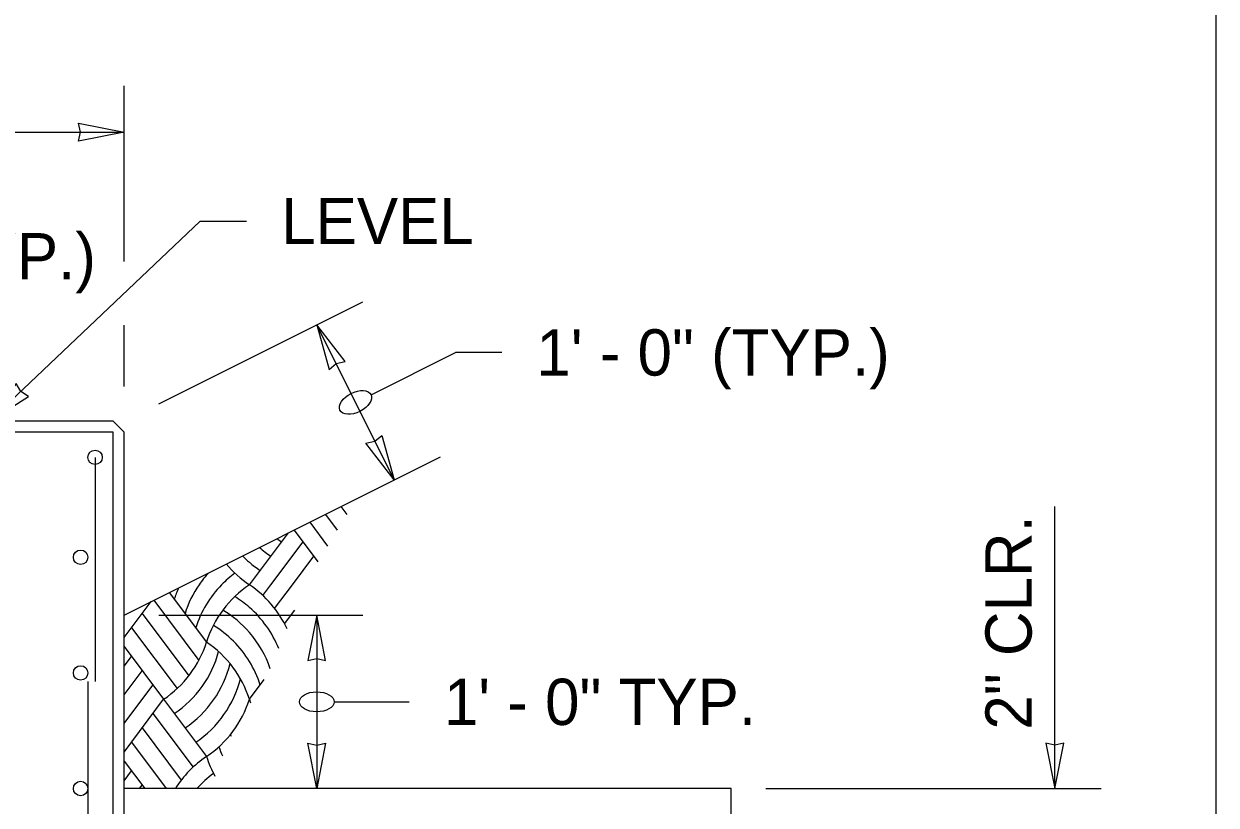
# Model space of a CAD drawing. Extents: x 99862 to 103151, y 100000 to 102076.
# Drawn here: x 102737.5 to 103150, y 101205 to 101475.3 of the extents above; entities that cross this region are included whole.
import ezdxf

# ---------------------------------------------------------------- set-up
doc = ezdxf.new("R2010")
doc.units = 0
for name, color, linetype in [('Level 10', 7, 'Continuous'), ('Level 15', 7, 'Continuous'), ('Level 2', 7, 'Continuous'), ('Level 20', 7, 'Continuous'), ('Level 5', 7, 'Continuous'), ('Level 60', 7, 'Continuous')]:
    doc.layers.add(name, color=color, linetype=linetype)

msp = doc.modelspace()

# ---------------------------------------------------------------- linework, layer by layer
at = {"layer": 'Level 10'}
for p, q in [((102762.17, 101325.3), (102762.17, 101247.8)), ((102762.17, 101325.3), (102762.17, 101247.8)), ((102759.67, 101247.8), (102759.67, 100936.99))]:
    msp.add_line(p, q, dxfattribs=at)
for centre in [(102762.17, 101325.3), (102762.17, 101325.3), (102757.17, 101290.72), (102757.17, 101290.72), (102757.17, 101250.72), (102757.17, 101250.72), (102757.17, 101210.71), (102757.17, 101210.71)]:
    msp.add_circle(centre, 2.5, dxfattribs=at)
at = {"layer": 'Level 15'}
for p, q in [((102772.17, 101393.03), (102772.17, 101453.8)), ((102772.17, 101393.03), (102772.17, 101453.8)), ((102592.17, 101437.8), (102772.17, 101437.8)), ((102592.17, 101437.8), (102772.17, 101437.8)), ((102725.6, 101337.8), (102798.56, 101407.05)), ((102725.6, 101337.8), (102798.56, 101407.05)), ((102798.56, 101407.05), (102814.56, 101407.05)), ((102798.56, 101407.05), (102814.56, 101407.05)), ((102784.17, 101343.8), (102854.84, 101379.13)), ((102784.17, 101343.8), (102854.84, 101379.13)), ((102772.17, 101349.8), (102772.17, 101370.97)), ((102772.17, 101349.8), (102772.17, 101370.97)), ((102865.67, 101317.46), (102838.84, 101371.13)), ((102865.67, 101317.46), (102838.84, 101371.13)), ((102857.62, 101346.98), (102886.84, 101361.59)), ((102857.62, 101346.98), (102886.84, 101361.59)), ((102902.84, 101361.59), (102886.84, 101361.59)), ((102902.84, 101361.59), (102886.84, 101361.59)), ((103094.17, 101210.71), (103094.17, 101308.24)), ((103094.17, 101210.71), (103094.17, 101308.24)), ((102784.17, 101270.71), (102854.84, 101270.71)), ((102784.17, 101270.71), (102854.84, 101270.71)), ((102838.84, 101270.71), (102838.84, 101210.71)), ((102838.84, 101270.71), (102838.84, 101210.71)), ((102844.84, 101240.71), (102870.84, 101240.71)), ((102844.84, 101240.71), (102870.84, 101240.71)), ((102994.17, 101210.71), (103110.17, 101210.71)), ((102994.17, 101210.71), (103110.17, 101210.71))]:
    msp.add_line(p, q, dxfattribs=at)
for points in [[(102772.17, 101437.8), (102756.45, 101434.71), (102757.17, 101437.8), (102756.45, 101440.88)], [(102772.17, 101437.8), (102756.45, 101434.71), (102757.17, 101437.8), (102756.45, 101440.88)], [(102838.84, 101371.13), (102843.11, 101355.69), (102845.55, 101357.72), (102848.63, 101358.44)], [(102838.84, 101371.13), (102843.11, 101355.69), (102845.55, 101357.72), (102848.63, 101358.44)], [(102725.6, 101337.8), (102739.13, 101346.38), (102736.48, 101348.12), (102734.89, 101350.86)], [(102865.67, 101317.46), (102855.88, 101330.15), (102858.96, 101330.88), (102861.4, 101332.91)], [(102865.67, 101317.46), (102855.88, 101330.15), (102858.96, 101330.88), (102861.4, 101332.91)], [(102838.84, 101270.71), (102835.75, 101254.99), (102838.84, 101255.72), (102841.92, 101254.99)], [(102838.84, 101270.71), (102835.75, 101254.99), (102838.84, 101255.72), (102841.92, 101254.99)], [(102838.84, 101210.71), (102835.75, 101226.44), (102838.84, 101225.71), (102841.92, 101226.44)], [(102838.84, 101210.71), (102835.75, 101226.44), (102838.84, 101225.71), (102841.92, 101226.44)], [(103094.17, 101210.71), (103097.26, 101226.44), (103094.17, 101225.71), (103091.09, 101226.44)], [(103094.17, 101210.71), (103097.26, 101226.44), (103094.17, 101225.71), (103091.09, 101226.44)]]:
    msp.add_lwpolyline(points, close=True, dxfattribs=at)
for centre, major_axis in [((102852.26, 101344.3), (5.37, 2.68)), ((102852.26, 101344.3), (5.37, 2.68)), ((102838.84, 101240.71), (6, 0)), ((102838.84, 101240.71), (6, 0))]:
    msp.add_ellipse(centre, major_axis=major_axis, ratio=0.57735, dxfattribs=at)
at = {"layer": 'Level 2'}
for p, q in [((102768.42, 101337.8), (102595.92, 101337.8)), ((102768.42, 101337.8), (102595.92, 101337.8)), ((102768.42, 101337.8), (102772.17, 101334.05)), ((102768.42, 101337.8), (102772.17, 101334.05)), ((102768.42, 101334.05), (102595.92, 101334.05)), ((102768.42, 101334.05), (102595.92, 101334.05)), ((102768.42, 101150.71), (102768.42, 101334.05)), ((102768.42, 101150.71), (102768.42, 101334.05)), ((102772.17, 101150.71), (102772.17, 101334.05)), ((102772.17, 101150.71), (102772.17, 101334.05)), ((102982.17, 101210.71), (102772.17, 101210.71)), ((102982.17, 101210.71), (102772.17, 101210.71)), ((102982.17, 100936.99), (102982.17, 101210.71)), ((102982.17, 100936.99), (102982.17, 101210.71))]:
    msp.add_line(p, q, dxfattribs=at)
at = {"layer": 'Level 5'}
for p, q in [((102772.17, 101270.71), (102881.67, 101325.46)), ((102772.17, 101270.71), (102881.67, 101325.46)), ((102841.83, 101305.55), (102845.93, 101300.09)), ((102841.83, 101305.55), (102845.93, 101300.09)), ((102847.23, 101308.25), (102849.26, 101305.55)), ((102847.23, 101308.25), (102849.26, 101305.55)), ((102836.44, 101302.85), (102842.6, 101294.62)), ((102836.44, 101302.85), (102842.6, 101294.62)), ((102815.56, 101281.18), (102829.03, 101299.15)), ((102815.56, 101281.18), (102829.03, 101299.15)), ((102831.04, 101300.15), (102839.28, 101289.16)), ((102831.04, 101300.15), (102839.28, 101289.16)), ((102822.99, 101281.18), (102834.12, 101296.03)), ((102822.99, 101281.18), (102834.12, 101296.03)), ((102830.41, 101281.18), (102837.83, 101291.08)), ((102830.41, 101281.18), (102837.83, 101291.08)), ((102820.21, 101277.49), (102822.99, 101281.18)), ((102820.21, 101277.49), (102822.99, 101281.18)), ((102824.29, 101273.02), (102830.41, 101281.18)), ((102824.29, 101273.02), (102830.41, 101281.18)), ((102782.44, 101275.85), (102798.04, 101255.05)), ((102782.44, 101275.85), (102798.04, 101255.05)), ((102787.84, 101278.55), (102800.71, 101261.38)), ((102787.84, 101278.55), (102800.71, 101261.38)), ((102772.17, 101262.93), (102781.52, 101275.39)), ((102772.17, 101262.93), (102781.52, 101275.39)), ((102827.74, 101267.72), (102831.3, 101272.46)), ((102827.74, 101267.72), (102831.3, 101272.46)), ((102778.44, 101271.28), (102794.59, 101249.74)), ((102778.44, 101271.28), (102794.59, 101249.74)), ((102774.73, 101266.33), (102790.52, 101245.28)), ((102774.73, 101266.33), (102790.52, 101245.28)), ((102772.17, 101259.84), (102785.86, 101241.58)), ((102772.17, 101259.84), (102785.86, 101241.58)), ((102772.17, 101253.03), (102774.73, 101256.43)), ((102772.17, 101253.03), (102774.73, 101256.43)), ((102772.17, 101243.13), (102778.44, 101251.48)), ((102772.17, 101243.13), (102778.44, 101251.48)), ((102815.56, 101241.58), (102820.7, 101248.43)), ((102815.56, 101241.58), (102820.7, 101248.43)), ((102772.17, 101233.23), (102782.15, 101246.53)), ((102772.17, 101233.23), (102782.15, 101246.53)), ((102772.17, 101223.33), (102785.86, 101241.58)), ((102772.17, 101223.33), (102785.86, 101241.58)), ((102785.86, 101241.58), (102800.71, 101221.78)), ((102785.86, 101241.58), (102800.71, 101221.78)), ((102782.15, 101236.63), (102796.06, 101218.09)), ((102782.15, 101236.63), (102796.06, 101218.09)), ((102778.44, 101231.68), (102791.98, 101213.63)), ((102778.44, 101231.68), (102791.98, 101213.63)), ((102774.73, 101226.73), (102786.74, 101210.71)), ((102774.73, 101226.73), (102786.74, 101210.71)), ((102772.17, 101220.24), (102779.32, 101210.71)), ((102772.17, 101220.24), (102779.32, 101210.71)), ((102772.17, 101213.43), (102774.73, 101216.83)), ((102772.17, 101213.43), (102774.73, 101216.83)), ((102777.56, 101210.71), (102778.44, 101211.89)), ((102777.56, 101210.71), (102778.44, 101211.89))]:
    msp.add_line(p, q, dxfattribs=at)
for centre, start, end in [((102847.66, 101327.22), 233.0882, 236.0964), ((102847.66, 101327.22), 233.0882, 236.0964), ((102843.95, 101322.27), 228.4612, 236.0964), ((102843.95, 101322.27), 228.4612, 236.0964), ((102836.52, 101312.37), 219.6058, 236.0964), ((102836.52, 101312.37), 219.6058, 236.0964), ((102840.23, 101317.32), 223.9793, 228.9599), ((102840.23, 101317.32), 223.9793, 228.9599), ((102840.23, 101317.32), 228.9599, 236.0964), ((102840.23, 101317.32), 228.9599, 236.0964), ((102829.1, 101259.89), 137.3252, 145.4911), ((102829.1, 101259.89), 137.3252, 145.4911), ((102832.81, 101254.94), 126.331, 135.7128), ((102832.81, 101254.94), 126.331, 135.7128), ((102825.39, 101264.84), 155.934, 162.3566), ((102825.39, 101264.84), 155.934, 162.3566), ((102829.1, 101259.89), 145.491, 162.3566), ((102829.1, 101259.89), 145.491, 162.3566), ((102832.81, 101254.94), 135.7127, 162.3566), ((102832.81, 101254.94), 135.7127, 162.3566), ((102836.52, 101249.99), 123.9036, 162.3566), ((102836.52, 101249.99), 123.9036, 162.3566), ((102794.6, 101249.99), 25.2358, 56.0963), ((102794.6, 101249.99), 25.2358, 56.0963), ((102790.89, 101245.04), 48.9597, 58.5465), ((102790.89, 101245.04), 48.9597, 58.5465), ((102787.18, 101240.09), 40.9413, 59.3021), ((102787.18, 101240.09), 40.9413, 59.3021), ((102790.89, 101245.04), 22.0575, 48.9597), ((102790.89, 101245.04), 22.0575, 48.9597), ((102783.46, 101235.14), 31.3316, 58.4874), ((102783.46, 101235.14), 31.3316, 58.4874), ((102787.18, 101240.09), 18.6907, 40.9414), ((102787.18, 101240.09), 18.6907, 40.9414), ((102764.9, 101272.77), 303.9036, 342.3566), ((102764.9, 101272.77), 303.9036, 342.3566), ((102779.75, 101230.19), 17.6434, 56.0964), ((102779.75, 101230.19), 17.6434, 56.0964), ((102768.61, 101267.82), 303.9036, 345.0113), ((102768.61, 101267.82), 303.9036, 345.0113), ((102772.33, 101262.87), 303.9036, 346.3199), ((102772.33, 101262.87), 303.9036, 346.3199), ((102783.46, 101235.14), 17.6434, 31.3317), ((102783.46, 101235.14), 17.6434, 31.3317), ((102776.04, 101257.92), 303.9036, 345.7713), ((102776.04, 101257.92), 303.9036, 345.7713), ((102779.75, 101252.97), 303.9036, 342.3566), ((102779.75, 101252.97), 303.9036, 342.3566), ((102851.37, 101252.97), 197.6435, 199.606), ((102851.37, 101252.97), 197.6435, 199.606), ((102847.66, 101248.02), 200.8778, 200.9878), ((102847.66, 101248.02), 200.8778, 200.9878), ((102843.95, 101243.07), 201.4344, 202.345), ((102843.95, 101243.07), 201.4344, 202.345), ((102840.23, 101238.12), 200.2432, 205.416), ((102840.23, 101238.12), 200.2432, 205.416), ((102821.67, 101190.6), 123.9036, 147.6293), ((102821.67, 101190.6), 123.9036, 147.6293), ((102836.52, 101233.17), 197.6434, 208.972), ((102836.52, 101233.17), 197.6434, 208.972), ((102825.39, 101185.65), 126.3063, 138.1551), ((102825.39, 101185.65), 126.3063, 138.1551)]:
    msp.add_arc(centre, 37.58, start, end, dxfattribs=at)
at = {"layer": 'Level 60'}
msp.add_line((103150, 100000), (103150, 102075), dxfattribs=at)

# ---------------------------------------------------------------- texts
at = {"layer": 'Level 20'}
for s, p in [('LEVEL', (102826.56, 101399.05)), ('(TYP.)', (102700.65, 101386.88)), ('1\' - 0" TYP.', (102882.84, 101232.71))]:
    msp.add_text(s, height=16, dxfattribs=at).set_placement(p)
for s, rotation, p in [('1\' - 0" (TYP.)', 360, (102914.84, 101353.59)), ('2" CLR.', 90, (103086.17, 101231.09))]:
    msp.add_text(s, height=16, rotation=rotation, dxfattribs=at).set_placement(p)

doc.saveas('drawing.dxf')
